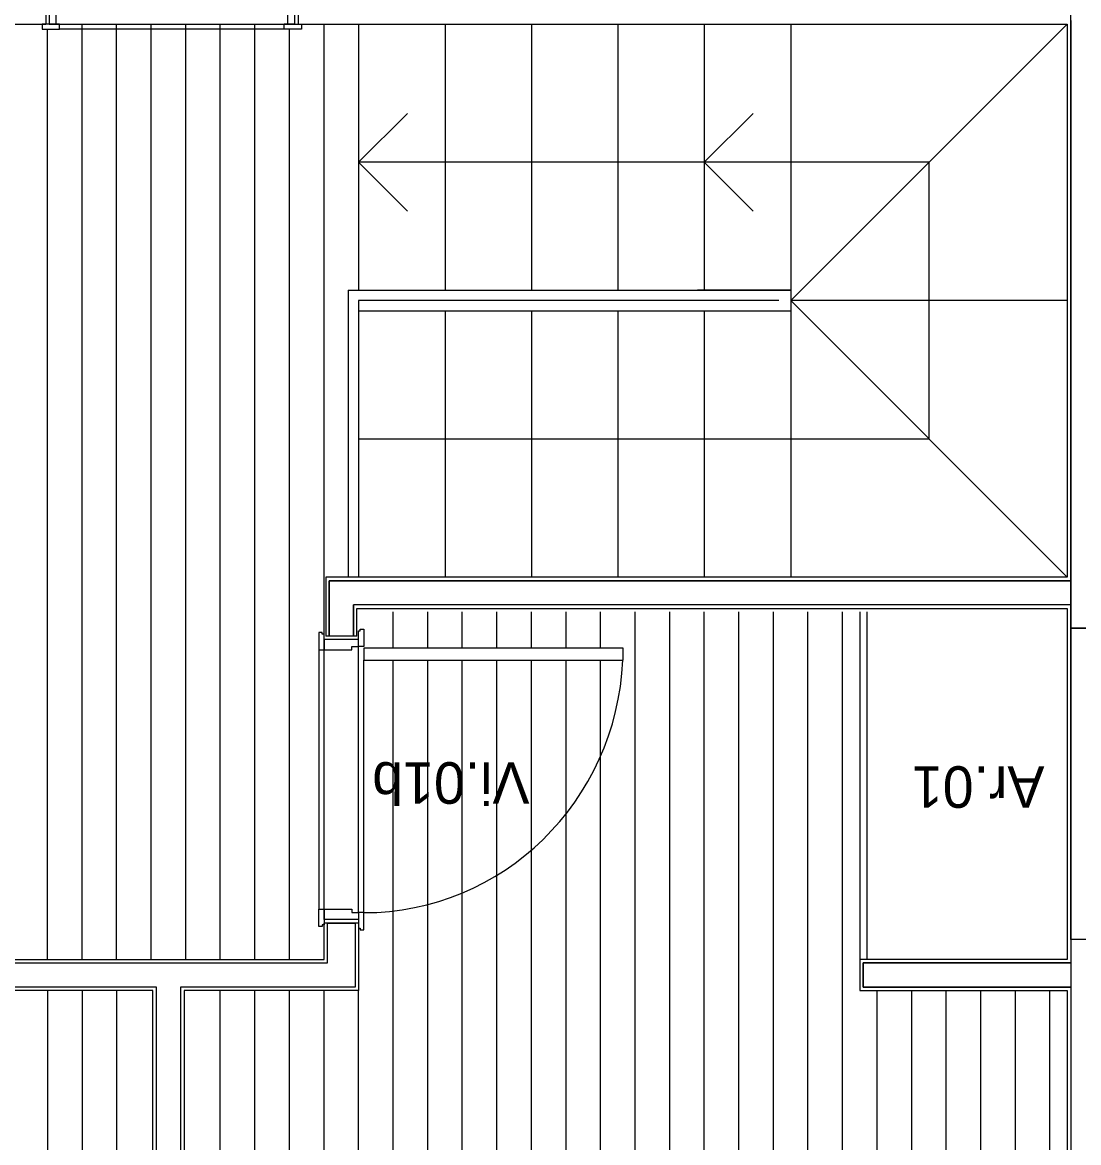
# Model space of a CAD drawing. Extents: x 1278 to 1356, y -253.7 to -224.
# Drawn here: x 1320.769 to 1323.824, y -243.659 to -240.419 of the extents above; entities that cross this region are included whole.
import ezdxf

# ---------------------------------------------------------------- set-up
doc = ezdxf.new("R2010")
doc.units = 0
for name, color, linetype in [('Level 1', 7, 'Continuous'), ('Level 10', 7, 'Continuous'), ('Level 13', 7, 'Continuous'), ('Level 2', 7, 'Continuous'), ('Level 4', 7, 'Continuous'), ('Level 40', 7, 'Continuous'), ('Level 65', 7, 'Continuous'), ('Level 66', 7, 'Continuous'), ('Level 67', 7, 'Continuous')]:
    doc.layers.add(name, color=color, linetype=linetype)

msp = doc.modelspace()

# ---------------------------------------------------------------- linework, layer by layer
at = {"layer": 'Level 1'}
for p, q in [((1320.836, -240.319), (1320.836, -240.424)), ((1321.566, -240.319), (1321.566, -240.424)), ((1323.801, -240.414), (1323.801, -242.034)), ((1323.801, -242.034), (1321.656, -242.034)), ((1321.656, -242.034), (1321.656, -242.194)), ((1321.726, -242.194), (1321.726, -242.104)), ((1323.801, -242.104), (1321.726, -242.104)), ((1323.801, -242.104), (1323.801, -243.139)), ((1321.736, -242.194), (1321.6464, -242.194)), ((1321.741, -243.024), (1321.641, -243.024)), ((1321.651, -243.139), (1321.651, -243.024)), ((1321.731, -243.024), (1321.731, -243.209)), ((1320.731, -243.139), (1321.651, -243.139)), ((1323.201, -243.139), (1323.201, -243.209)), ((1323.801, -243.139), (1323.201, -243.139)), ((1321.156, -243.209), (1320.651, -243.209)), ((1321.156, -246.584), (1321.156, -243.209)), ((1321.226, -243.209), (1321.226, -246.584)), ((1321.731, -243.209), (1321.226, -243.209)), ((1323.201, -243.209), (1323.801, -243.209))]:
    msp.add_line(p, q, dxfattribs=at)
at = {"layer": 'Level 10'}
for p, q in [((1320.841, -243.129), (1320.841, -240.439)), ((1320.876, -240.424), (1321.526, -240.424)), ((1320.941, -243.129), (1320.941, -240.424)), ((1321.041, -243.129), (1321.041, -240.424)), ((1321.141, -243.129), (1321.141, -240.424)), ((1321.241, -243.129), (1321.241, -240.424)), ((1321.341, -243.129), (1321.341, -240.424)), ((1321.441, -243.129), (1321.441, -240.424)), ((1321.541, -243.129), (1321.541, -240.439)), ((1321.641, -242.194), (1321.641, -240.424)), ((1321.841, -242.229), (1321.841, -242.124)), ((1321.941, -242.229), (1321.941, -242.124)), ((1322.041, -242.229), (1322.041, -242.124)), ((1322.141, -242.229), (1322.141, -242.124)), ((1322.241, -242.229), (1322.241, -242.124)), ((1322.341, -242.229), (1322.341, -242.124)), ((1322.441, -242.229), (1322.441, -242.124)), ((1322.541, -246.574), (1322.541, -242.124)), ((1322.641, -246.574), (1322.641, -242.124)), ((1322.741, -246.574), (1322.741, -242.124)), ((1322.841, -246.574), (1322.841, -242.124)), ((1322.941, -246.574), (1322.941, -242.124)), ((1323.041, -246.574), (1323.041, -242.124)), ((1323.141, -246.574), (1323.141, -242.124)), ((1321.741, -242.994), (1321.741, -242.224)), ((1321.641, -242.984), (1321.641, -242.234)), ((1321.841, -246.574), (1321.841, -242.264)), ((1321.941, -246.574), (1321.941, -242.264)), ((1322.041, -246.574), (1322.041, -242.264)), ((1322.141, -246.574), (1322.141, -242.264)), ((1322.241, -246.574), (1322.241, -242.264)), ((1322.341, -246.574), (1322.341, -242.264)), ((1322.441, -246.574), (1322.441, -242.264)), ((1320.841, -243.219), (1320.841, -246.574)), ((1320.941, -243.219), (1320.941, -246.574)), ((1321.041, -243.219), (1321.041, -246.574)), ((1321.341, -246.574), (1321.341, -243.219)), ((1321.441, -246.574), (1321.441, -243.219)), ((1321.541, -246.574), (1321.541, -243.219)), ((1321.641, -246.574), (1321.641, -243.219)), ((1321.741, -246.574), (1321.741, -243.219)), ((1323.241, -246.574), (1323.241, -243.219)), ((1323.341, -246.574), (1323.341, -243.219)), ((1323.441, -246.574), (1323.441, -243.219)), ((1323.541, -246.574), (1323.541, -243.219)), ((1323.641, -246.574), (1323.641, -243.219)), ((1323.741, -246.574), (1323.741, -243.219))]:
    msp.add_line(p, q, dxfattribs=at)
at = {"layer": 'Level 13'}
for p, q in [((1320.846, -240.319), (1320.846, -240.424)), ((1320.866, -240.424), (1320.866, -240.319)), ((1321.536, -240.424), (1321.536, -240.319)), ((1321.556, -240.319), (1321.556, -240.424)), ((1320.876, -240.424), (1320.826, -240.424)), ((1320.826, -240.424), (1320.826, -240.439)), ((1320.826, -240.439), (1320.876, -240.439)), ((1320.846, -240.424), (1320.876, -240.424)), ((1320.876, -240.439), (1320.876, -240.424)), ((1321.556, -240.424), (1321.526, -240.424)), ((1321.526, -240.424), (1321.576, -240.424)), ((1321.526, -240.439), (1321.526, -240.424)), ((1321.576, -240.439), (1321.526, -240.439)), ((1321.576, -240.424), (1321.576, -240.439)), ((1323.191, -242.124), (1323.191, -243.129)), ((1323.211, -242.124), (1323.211, -243.129)), ((1321.626, -242.184), (1321.626, -242.234)), ((1321.636, -242.184), (1321.626, -242.184)), ((1321.636, -242.189), (1321.636, -242.184)), ((1321.641, -242.189), (1321.636, -242.189)), ((1321.641, -242.234), (1321.641, -242.189)), ((1321.741, -242.224), (1321.741, -242.179)), ((1321.741, -242.179), (1321.746, -242.179)), ((1321.746, -242.179), (1321.746, -242.174)), ((1321.746, -242.174), (1321.756, -242.174)), ((1321.756, -242.174), (1321.756, -242.224)), ((1321.741, -242.204), (1321.641, -242.204)), ((1321.641, -242.204), (1321.641, -242.234)), ((1321.721, -242.234), (1321.721, -242.224)), ((1321.721, -242.224), (1321.741, -242.224)), ((1321.741, -242.224), (1321.741, -242.204)), ((1321.756, -242.224), (1321.741, -242.224)), ((1321.626, -242.234), (1321.641, -242.234)), ((1321.641, -242.234), (1321.721, -242.234)), ((1322.506, -242.229), (1321.756, -242.229)), ((1321.756, -242.229), (1321.756, -242.264)), ((1322.506, -242.264), (1322.506, -242.229)), ((1321.756, -242.264), (1322.506, -242.264)), ((1321.626, -243.034), (1321.626, -242.984)), ((1321.626, -242.984), (1321.641, -242.984)), ((1321.641, -242.984), (1321.641, -243.029)), ((1321.641, -243.014), (1321.641, -242.984)), ((1321.641, -242.984), (1321.721, -242.984)), ((1321.721, -242.984), (1321.721, -242.994)), ((1321.721, -242.994), (1321.741, -242.994)), ((1321.741, -242.994), (1321.741, -243.014)), ((1321.756, -242.994), (1321.741, -242.994)), ((1321.741, -242.994), (1321.741, -243.039)), ((1321.756, -243.044), (1321.756, -242.994)), ((1321.636, -243.034), (1321.626, -243.034)), ((1321.641, -243.029), (1321.636, -243.029)), ((1321.636, -243.029), (1321.636, -243.034)), ((1321.741, -243.014), (1321.641, -243.014)), ((1321.741, -243.039), (1321.746, -243.039)), ((1321.746, -243.039), (1321.746, -243.044)), ((1321.746, -243.044), (1321.756, -243.044))]:
    msp.add_line(p, q, dxfattribs=at)
at = {"layer": 'Level 2'}
for p, q in [((1321.741, -240.424), (1321.741, -241.194)), ((1321.991, -240.424), (1321.991, -241.194)), ((1322.241, -240.424), (1322.241, -241.194)), ((1322.491, -240.424), (1322.491, -241.194)), ((1322.741, -240.424), (1322.741, -241.194)), ((1322.991, -240.424), (1322.991, -241.194)), ((1322.991, -241.224), (1323.791, -240.424)), ((1321.8824, -240.6826), (1321.741, -240.824)), ((1322.8824, -240.6826), (1322.741, -240.824)), ((1321.8824, -240.9654), (1321.741, -240.824)), ((1323.391, -240.824), (1321.741, -240.824)), ((1323.391, -240.824), (1322.741, -240.824)), ((1323.391, -240.824), (1322.741, -240.824)), ((1322.8824, -240.9654), (1322.741, -240.824)), ((1323.391, -240.824), (1323.391, -241.624)), ((1321.711, -241.194), (1321.711, -242.024)), ((1321.711, -241.194), (1322.991, -241.194)), ((1321.741, -241.224), (1321.741, -242.024)), ((1321.741, -241.224), (1321.741, -242.024)), ((1321.741, -241.224), (1321.741, -242.024)), ((1321.741, -241.224), (1321.741, -242.024)), ((1321.741, -241.224), (1321.741, -242.024)), ((1322.9564, -241.224), (1321.741, -241.224)), ((1322.991, -241.194), (1322.721, -241.194)), ((1322.9564, -241.224), (1322.721, -241.224)), ((1322.991, -241.194), (1322.991, -241.254)), ((1323.791, -241.224), (1322.991, -241.224)), ((1322.991, -241.224), (1323.791, -242.024)), ((1322.991, -241.254), (1321.741, -241.254)), ((1321.991, -241.254), (1321.991, -242.024)), ((1322.241, -241.254), (1322.241, -242.024)), ((1322.491, -241.254), (1322.491, -242.024)), ((1322.741, -241.254), (1322.741, -242.024)), ((1322.991, -241.254), (1322.991, -242.024)), ((1321.741, -241.624), (1323.391, -241.624))]:
    msp.add_line(p, q, dxfattribs=at)
at = {"layer": 'Level 4'}
for p, q in [((1321.526, -240.439), (1320.876, -240.439)), ((1321.626, -242.234), (1321.626, -242.984)), ((1321.756, -242.994), (1321.756, -242.264))]:
    msp.add_line(p, q, dxfattribs=at)
msp.add_ellipse((1321.756, -242.2308), major_axis=(0, 0.7632), ratio=0.982661, start_param=3.141593, end_param=4.668897, dxfattribs=at)
at = {"layer": 'Level 65'}
for p, q in [((1320.736, -240.424), (1320.836, -240.424)), ((1321.566, -240.424), (1323.791, -240.424)), ((1323.791, -240.424), (1323.791, -242.024)), ((1321.646, -242.024), (1321.646, -242.194)), ((1323.791, -242.024), (1321.646, -242.024)), ((1321.736, -242.194), (1321.736, -242.114)), ((1321.736, -242.114), (1323.791, -242.114)), ((1323.791, -242.114), (1323.791, -243.129)), ((1321.641, -243.129), (1321.641, -243.024)), ((1321.741, -243.024), (1321.741, -243.219)), ((1320.741, -243.129), (1321.641, -243.129)), ((1323.191, -243.129), (1323.191, -243.219)), ((1323.791, -243.129), (1323.191, -243.129)), ((1321.146, -243.219), (1320.641, -243.219)), ((1321.146, -246.574), (1321.146, -243.219)), ((1321.741, -243.219), (1321.236, -243.219)), ((1321.236, -243.219), (1321.236, -246.574)), ((1323.191, -243.219), (1323.791, -243.219)), ((1323.791, -243.219), (1323.791, -246.924))]:
    msp.add_line(p, q, dxfattribs=at)
at = {"layer": 'Level 66'}
msp.add_line((1323.801, -243.209), (1323.801, -246.914), dxfattribs=at)
msp.add_lwpolyline([(1324.031, -243.0713), (1323.801, -243.0713), (1323.801, -242.1713), (1324.031, -242.1713)], close=True, dxfattribs=at)
at = {"layer": 'Level 67'}
for points in [[(1323.871, -242.1713), (1323.801, -242.1713), (1323.801, -236.7713), (1323.871, -236.7713), (1323.871, -242.1713)], [(1323.801, -242.104), (1321.726, -242.104), (1321.726, -242.194), (1321.656, -242.194), (1321.656, -242.034), (1323.801, -242.034)], [(1321.226, -246.584), (1321.156, -246.584), (1321.156, -243.209), (1320.651, -243.209), (1320.651, -243.024), (1320.731, -243.024), (1320.731, -243.139), (1321.651, -243.139), (1321.651, -243.024), (1321.731, -243.024), (1321.731, -243.209), (1321.226, -243.209)], [(1323.871, -243.0713), (1323.801, -243.0713), (1323.801, -245.8713), (1323.871, -245.8713)], [(1323.801, -243.209), (1323.201, -243.209), (1323.201, -243.139), (1323.801, -243.139)]]:
    msp.add_lwpolyline(points, close=True, dxfattribs=at)

# ---------------------------------------------------------------- texts
at = {"layer": 'Level 40'}
for s, p in [('Vi.01b', (1322.2355, -242.5589)), ('Ar.01', (1323.725, -242.5706))]:
    msp.add_text(s, height=0.12, rotation=180, dxfattribs=at).set_placement(p)

doc.saveas('drawing.dxf')
